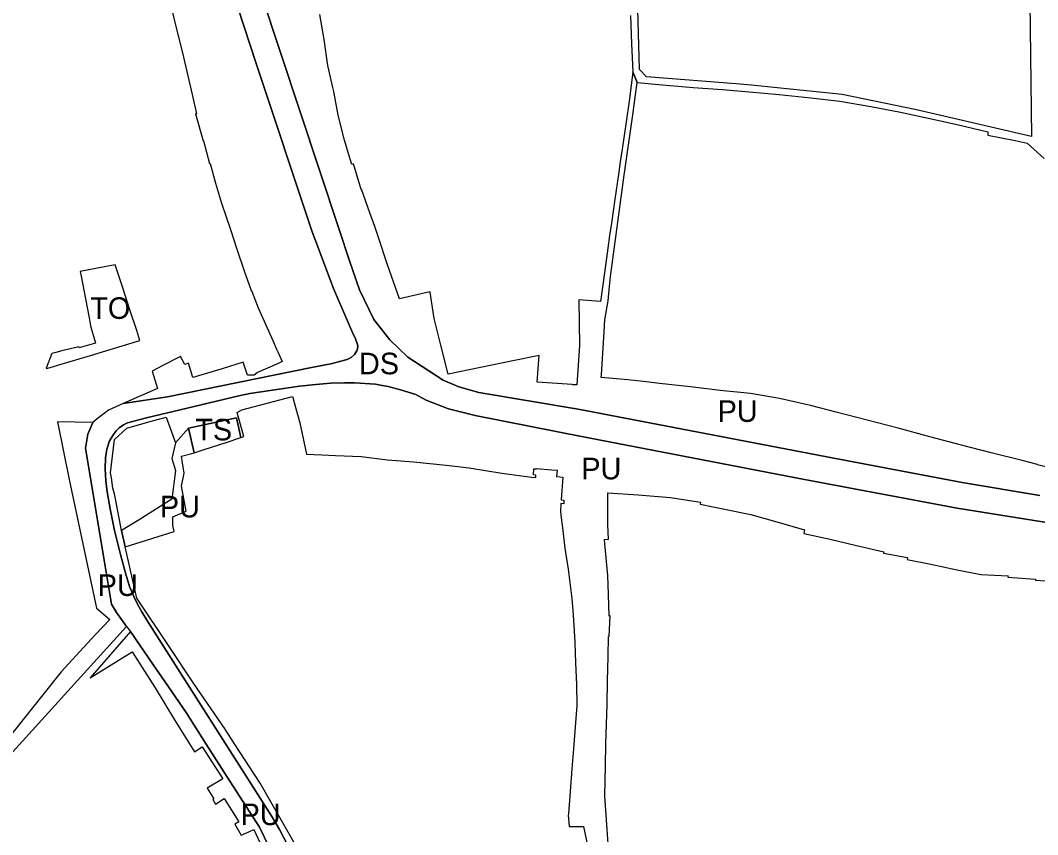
# Model space of a CAD drawing. Extents: x -521047 to -518054, y -1194945 to -1189555.
# Drawn here: x -520049.7 to -519578, y -1191998.4 to -1191620.9 of the extents above; entities that cross this region are included whole.
import ezdxf

# ---------------------------------------------------------------- set-up
doc = ezdxf.new("R2010")
doc.units = 0
for name, color, linetype in [('90320013', 7, 'Continuous'), ('90410013', 7, 'Continuous'), ('90430013', 7, 'Continuous'), ('90450013', 7, 'Continuous')]:
    doc.layers.add(name, color=color, linetype=linetype)

msp = doc.modelspace()

# ---------------------------------------------------------------- linework, layer by layer
at = {"layer": '90320013'}
for points in [[(-519951.7, -1191606.35), (-519940.4, -1191640.9), (-519914.37, -1191718.97), (-519913.17, -1191722.18), (-519904.59, -1191745.15), (-519904.11, -1191746.27), (-519899.31, -1191757.43), (-519895.67, -1191765.56), (-519894.32, -1191768.58), (-519893.35, -1191771.13), (-519893.23, -1191772.14), (-519893.35, -1191773.17), (-519893.72, -1191774.12), (-519894.86, -1191775.8), (-519896.34, -1191777.19), (-519898.15, -1191778.09), (-519905.8, -1191780.08), (-519914.66, -1191781.8), (-519932.25, -1191785.42), (-519981.45, -1191795.45), (-520002.03, -1191798.56), (-520008.78, -1191801.57), (-520014.11, -1191805.56), (-520016.05, -1191807.34), (-520018.47, -1191812.73), (-520019.56, -1191819.22), (-520007.5, -1191891.48), (-520005.16, -1191895.35), (-520000.5, -1191901.98), (-519998.7, -1191904.19), (-519987.91, -1191919.82), (-519982.66, -1191927.42), (-519972.8, -1191941.71), (-519963.53, -1191956.53), (-519954, -1191971.37), (-519938.91, -1191994.89), (-519934.5, -1192003.88)], [(-519577.08, -1191841.18), (-519613.12, -1191835.08), (-519672.49, -1191823.8), (-519791.06, -1191801.12), (-519837.21, -1191793.39), (-519846.4, -1191790.82), (-519853.69, -1191787.65), (-519869.99, -1191777.11), (-519878.44, -1191768.99), (-519885.81, -1191759.52), (-519892.42, -1191745.79), (-519897.31, -1191731.93), (-519901.82, -1191718.32), (-519929.33, -1191635.28), (-519937.84, -1191609.04)], [(-519925.88, -1192003.11), (-519929.61, -1191996.06), (-519933.13, -1191990.02), (-519990.79, -1191899.38), (-519993.42, -1191895.12), (-519995.33, -1191891.61), (-519997.06, -1191888.01), (-519999.05, -1191883.41), (-520000.86, -1191877.69), (-520003.3, -1191868.48), (-520006.03, -1191857.38), (-520008.1, -1191847.41), (-520009.43, -1191839.41), (-520010.05, -1191834.36), (-520010.35, -1191828.8), (-520010.25, -1191823.71), (-520009.68, -1191819.64), (-520008.43, -1191815.77), (-520006.6, -1191812.84), (-520005.35, -1191811.24), (-520003.94, -1191809.78), (-520001.94, -1191808.4), (-520000.09, -1191807.54), (-519991.21, -1191805.18), (-519972.41, -1191800.67), (-519948.39, -1191794.95), (-519943.26, -1191793.93), (-519920.23, -1191790.55), (-519912.66, -1191789.74), (-519905.97, -1191789.15), (-519899.49, -1191788.87), (-519894.81, -1191788.88), (-519885.06, -1191789.58), (-519881.98, -1191790.14), (-519879.25, -1191790.68), (-519873.45, -1191792.22), (-519866.29, -1191794.43), (-519861.49, -1191796.98), (-519851.18, -1191801.06), (-519838.85, -1191804.06), (-519800.55, -1191811.63), (-519797.43, -1191812.24), (-519781.44, -1191815.36), (-519686.16, -1191833.74), (-519615.32, -1191846.99), (-519568.13, -1191854.57)]]:
    msp.add_lwpolyline(points, dxfattribs=at)
at = {"layer": '90410013'}
msp.add_lwpolyline([(-519969.19, -1191821.4), (-519964.89, -1191820), (-519964.46, -1191819.86), (-519954.33, -1191816.57), (-519947.47, -1191814.34), (-519949.53, -1191805.16), (-519971.77, -1191809.96), (-519969.19, -1191821.4)], dxfattribs=at)
at = {"layer": '90430013'}
msp.add_lwpolyline([(-519994.31, -1191769.26), (-519995.78, -1191764.75), (-519998.92, -1191755.07), (-520002.37, -1191744.43), (-520005.69, -1191734.2), (-520010.73, -1191735.19), (-520021.93, -1191737.38), (-520021.53, -1191739.43), (-520018.69, -1191754.09), (-520017.89, -1191758.75), (-520017.24, -1191762.51), (-520014.83, -1191770.51), (-520022.41, -1191772.79), (-520022.59, -1191772.19), (-520028.49, -1191773.6), (-520029.39, -1191773.82), (-520033.33, -1191774.87), (-520035.11, -1191775.34), (-520037.79, -1191782.2), (-520037.58, -1191782.36), (-520034.75, -1191781.51), (-520031.92, -1191780.65), (-520017.18, -1191776.24), (-520002.44, -1191771.82), (-519994.31, -1191769.26)], dxfattribs=at)
at = {"layer": '90450013'}
for points in [[(-519583.09, -1191499.99), (-519580.83, -1191674.78), (-519586.89, -1191673.37), (-519634.15, -1191662.4), (-519668.73, -1191655.24), (-519698.78, -1191652.19), (-519710.66, -1191650.95), (-519716.05, -1191650.55), (-519759.34, -1191647.09), (-519762.65, -1191643.76), (-519765.6, -1191537.51)], [(-519979.91, -1191614.16), (-519977.29, -1191625.06), (-519974.61, -1191635.89), (-519972.14, -1191646.55), (-519970.12, -1191655.32), (-519968.1, -1191664.17), (-519968.45, -1191664.24), (-519965.03, -1191676.77), (-519964.74, -1191676.7), (-519962.09, -1191687.28), (-519961.74, -1191687.2), (-519959.25, -1191696.44), (-519956.45, -1191705.61), (-519952.36, -1191717.83), (-519949.34, -1191727.04), (-519945.95, -1191736.95), (-519942.66, -1191746.15), (-519942.51, -1191746.12), (-519939.38, -1191754.11), (-519932.66, -1191769.26), (-519930.88, -1191773.31), (-519930.29, -1191774.52), (-519928.26, -1191779.12), (-519930.56, -1191780.13), (-519939.82, -1191784.22), (-519939.96, -1191784.28), (-519941.27, -1191785.44), (-519944.46, -1191785.36), (-519946.34, -1191779.4), (-519956.07, -1191782.43), (-519969.69, -1191786.44), (-519971.72, -1191779.87), (-519973.38, -1191780.42), (-519975.46, -1191776.81), (-519983.97, -1191781.13), (-519988.61, -1191783.49), (-519986.18, -1191791.5), (-520002.03, -1191798.56), (-519981.45, -1191795.45), (-519932.25, -1191785.42), (-519914.66, -1191781.8), (-519905.8, -1191780.08), (-519898.15, -1191778.09), (-519896.34, -1191777.19), (-519894.86, -1191775.8), (-519893.72, -1191774.12), (-519893.35, -1191773.17), (-519893.23, -1191772.14), (-519893.35, -1191771.13), (-519894.32, -1191768.58), (-519895.67, -1191765.56), (-519899.31, -1191757.43), (-519904.11, -1191746.27), (-519904.59, -1191745.15), (-519913.17, -1191722.18), (-519914.37, -1191718.97), (-519940.4, -1191640.9), (-519951.7, -1191606.35)], [(-519937.84, -1191609.04), (-519929.33, -1191635.28), (-519901.82, -1191718.32), (-519897.31, -1191731.93), (-519892.42, -1191745.79), (-519885.81, -1191759.52), (-519878.44, -1191768.99), (-519869.99, -1191777.11), (-519853.69, -1191787.65), (-519846.4, -1191790.82), (-519837.21, -1191793.39), (-519791.06, -1191801.12), (-519672.49, -1191823.8), (-519613.12, -1191835.08), (-519577.08, -1191841.18)], [(-519857.83, -1191759.18), (-519859.76, -1191746.93), (-519859.79, -1191746.71), (-519873.86, -1191750.05), (-519879.44, -1191734.23), (-519883.67, -1191721.51), (-519885.35, -1191716.54), (-519887.63, -1191710.07), (-519891.52, -1191699.22), (-519891.75, -1191699.3), (-519895.27, -1191687.47), (-519896.1, -1191687.72), (-519897.78, -1191682.21), (-519899.39, -1191676.45), (-519902.39, -1191664.91), (-519904.44, -1191653.91), (-519904.97, -1191651.47), (-519905.14, -1191650.69), (-519907.1, -1191641.81), (-519908.85, -1191629.77), (-519910.89, -1191618.15)], [(-519766.89, -1191618.67), (-519766.35, -1191631.77), (-519765.78, -1191644.8), (-519763.68, -1191649.71), (-519752.06, -1191650.85), (-519744.88, -1191651.4), (-519737.81, -1191651.98), (-519724.23, -1191652.91), (-519711.85, -1191654), (-519697.86, -1191655.3), (-519683.18, -1191656.8), (-519669.7, -1191658.43), (-519655.45, -1191660.89), (-519641.67, -1191663.45), (-519628.05, -1191666.43), (-519614.74, -1191669.31), (-519601.15, -1191672.57), (-519601.22, -1191674.07)], [(-519570.61, -1191828.79), (-519578.11, -1191827), (-519578.06, -1191826.76), (-519585.29, -1191825.02), (-519599.53, -1191821.47), (-519613.42, -1191817.84), (-519627.98, -1191813.98), (-519642.75, -1191809.97), (-519657.16, -1191806.23), (-519671.44, -1191802.55), (-519683.4, -1191799.48), (-519697.75, -1191796.23), (-519711.2, -1191793.91), (-519725.26, -1191792.48), (-519738.98, -1191790.84), (-519753.35, -1191789.21), (-519760.76, -1191788.37), (-519768.03, -1191787.55), (-519780.42, -1191786.48), (-519780.33, -1191785.08), (-519779.24, -1191767.92), (-519778.72, -1191759.69), (-519777.16, -1191750.99), (-519776.57, -1191744.36), (-519776.12, -1191739.58), (-519769.69, -1191692.63), (-519765.97, -1191665.84), (-519763.68, -1191649.71), (-519765.78, -1191644.8), (-519767.31, -1191657.3), (-519769.05, -1191669.09), (-519770.71, -1191680.67), (-519771.54, -1191686.47), (-519772.38, -1191692.31), (-519774.06, -1191703.84), (-519775.69, -1191714.88), (-519776.58, -1191720.64), (-519777.34, -1191726.5), (-519778.77, -1191736.84), (-519780.68, -1191751.27), (-519790.84, -1191750.42), (-519790.49, -1191771.67), (-519791.66, -1191789.94), (-519793.49, -1191789.8), (-519793.87, -1191789.77), (-519810.07, -1191788.65), (-519809.2, -1191776.23), (-519821.34, -1191778.8), (-519851.31, -1191784.91), (-519854.69, -1191771.56), (-519857.83, -1191759.18)], [(-519601.22, -1191674.07), (-519588.45, -1191676.67), (-519582.88, -1191677.87), (-519574.98, -1191684.89)], [(-519568.13, -1191854.57), (-519615.32, -1191846.99), (-519686.16, -1191833.74), (-519781.44, -1191815.36), (-519797.43, -1191812.24), (-519800.55, -1191811.63), (-519838.85, -1191804.06), (-519851.18, -1191801.06), (-519861.49, -1191796.98), (-519866.29, -1191794.43), (-519873.45, -1191792.22), (-519879.25, -1191790.68), (-519881.98, -1191790.14), (-519885.06, -1191789.58), (-519894.81, -1191788.88), (-519899.49, -1191788.87), (-519905.97, -1191789.15), (-519912.66, -1191789.74), (-519920.23, -1191790.55), (-519943.26, -1191793.93), (-519948.39, -1191794.95), (-519972.41, -1191800.67), (-519991.21, -1191805.18), (-520000.09, -1191807.54), (-520001.94, -1191808.4), (-520003.94, -1191809.78), (-520005.35, -1191811.24), (-520006.6, -1191812.84), (-520008.43, -1191815.77), (-520009.68, -1191819.64), (-520010.25, -1191823.71), (-520010.35, -1191828.8), (-520010.05, -1191834.36), (-520009.43, -1191839.41), (-520008.1, -1191847.41), (-520006.03, -1191857.38), (-520003.3, -1191868.48), (-520000.86, -1191877.69), (-519999.05, -1191883.41), (-519997.06, -1191888.01), (-519995.33, -1191891.61), (-519993.42, -1191895.12), (-519990.79, -1191899.38), (-519933.13, -1191990.02), (-519929.61, -1191996.06), (-519925.88, -1192003.11)], [(-519922.3, -1192002.97), (-519926.15, -1191996.16), (-519929.81, -1191989.73), (-519938.46, -1191974.54), (-519950.46, -1191956.33), (-519954.62, -1191949.85), (-519954.81, -1191949.55), (-519969.38, -1191928.14), (-519980.73, -1191911.17), (-519995.77, -1191888.7), (-520001.16, -1191864.95), (-520002.87, -1191857.4), (-520004.91, -1191846.02), (-520006.13, -1191840.44), (-520006.77, -1191837.77), (-520007.53, -1191832.99), (-520007.87, -1191830.72), (-520006.13, -1191815.28), (-520000.29, -1191809.99), (-519990.1, -1191807.06), (-519982.11, -1191804.83), (-519977.82, -1191816.74), (-519971.77, -1191809.96), (-519949.53, -1191805.16), (-519947.47, -1191814.34), (-519946.08, -1191813.89), (-519949.17, -1191802.72), (-519947.02, -1191801.53), (-519923.55, -1191795.32), (-519920.18, -1191807.45), (-519916.99, -1191822.06), (-519910, -1191822.35), (-519903.53, -1191822.7), (-519891.77, -1191823.12), (-519879.47, -1191824.6), (-519867.4, -1191825.52), (-519859.82, -1191826.39), (-519852.26, -1191827.17), (-519841.63, -1191828.37), (-519826.51, -1191830.83), (-519812.65, -1191832.65), (-519810.72, -1191832.9), (-519810.64, -1191831.71), (-519811.81, -1191831.63), (-519811.64, -1191828.75), (-519810.47, -1191828.81), (-519810.4, -1191828.64), (-519803.44, -1191829.29), (-519800.86, -1191829.48), (-519801.12, -1191832.4), (-519798.26, -1191832.6), (-519799.02, -1191843.18), (-519797.75, -1191843.28), (-519797.78, -1191845.05), (-519799.16, -1191844.95), (-519799.31, -1191848.53), (-519799.09, -1191850.3), (-519798.21, -1191857.36), (-519797.26, -1191865.55), (-519795.65, -1191875.39), (-519794.06, -1191888.87), (-519793.57, -1191894.67), (-519793.21, -1191898.99), (-519792.58, -1191909.1), (-519792.46, -1191914.09), (-519792.35, -1191918.76), (-519791.81, -1191928.79), (-519791.7, -1191938.6), (-519792.42, -1191948.53), (-519793.24, -1191958.55), (-519793.98, -1191967.86), (-519794.81, -1191978.45), (-519795.61, -1191988.68), (-519795.66, -1191989.32), (-519795.2, -1191994.6), (-519788.63, -1191994.63), (-519786.7, -1192003.43)], [(-520055.94, -1191954.58), (-520056.08, -1191954.75), (-520059.24, -1191958.73), (-520064.17, -1191960.26), (-520060.15, -1191966.67), (-520056.79, -1191961.78), (-520054.76, -1191961.68), (-520027.63, -1191931.83), (-520000.5, -1191901.98), (-520005.16, -1191895.35), (-520007.5, -1191891.48), (-520019.56, -1191819.22), (-520018.47, -1191812.73), (-520016.05, -1191807.34), (-520032.53, -1191806.97), (-520029.72, -1191820.71), (-520027.04, -1191833.79), (-520014.4, -1191893.4), (-520008.2, -1191898.59), (-520015.01, -1191905.83), (-520030.81, -1191922.99), (-520052.53, -1191950.29), (-520055.94, -1191954.58)], [(-519969.19, -1191821.4), (-519971.77, -1191809.96), (-519977.82, -1191816.74), (-519979.51, -1191824.01), (-519977.77, -1191829.65), (-519979.5, -1191842.89), (-519984.85, -1191846.32), (-519994.64, -1191852.42), (-520002.87, -1191857.4), (-520001.16, -1191864.95), (-519978.42, -1191857.87), (-519979.08, -1191855.05), (-519979.08, -1191851.13), (-519972.88, -1191848.39), (-519974.94, -1191836.82), (-519973.76, -1191830.79), (-519974.61, -1191826.1), (-519975, -1191822.92), (-519970.16, -1191821.74), (-519969.19, -1191821.4)], [(-519777.19, -1192002.68), (-519778.7, -1191980.47), (-519778.43, -1191966.53), (-519778.22, -1191956.26), (-519777.71, -1191938.09), (-519777.42, -1191927.06), (-519777.14, -1191915.84), (-519777, -1191906.55), (-519776.67, -1191906.56), (-519776.29, -1191897.03), (-519776.74, -1191897.06), (-519777.02, -1191887.04), (-519777.4, -1191878.33), (-519778.7, -1191863.57), (-519778.81, -1191861.51), (-519777.05, -1191861.35), (-519777.39, -1191854.74), (-519777.26, -1191839.95), (-519763.31, -1191840.91), (-519748.24, -1191842.1), (-519734.35, -1191844.34), (-519734.51, -1191845.18), (-519722.48, -1191847.67), (-519710.96, -1191849.95), (-519698.96, -1191853.36), (-519686.19, -1191857.13), (-519686.46, -1191858.75), (-519674.32, -1191861.45), (-519662.1, -1191864.32), (-519649.44, -1191867.3), (-519649.57, -1191867.84), (-519638.43, -1191869.9), (-519638.61, -1191870.85), (-519627.5, -1191873.03), (-519616.1, -1191875.45), (-519604.45, -1191877.74), (-519591.76, -1191878.43), (-519591.8, -1191878.98), (-519578.97, -1191879.98), (-519579, -1191880.45), (-519565.6, -1191881.32)], [(-519934.5, -1192003.88), (-519938.91, -1191994.89), (-519954, -1191971.37), (-519963.53, -1191956.53), (-519972.8, -1191941.71), (-519982.66, -1191927.42), (-519987.91, -1191919.82), (-519998.7, -1191904.19), (-520017.32, -1191925.76), (-519997.93, -1191913.6), (-519992.15, -1191922.67), (-519987.2, -1191930.37), (-519978.25, -1191945.23), (-519968.94, -1191959.95), (-519965.42, -1191957.72), (-519960.63, -1191965.1), (-519955.84, -1191972.48), (-519963.05, -1191976.83), (-519959.95, -1191981.75), (-519960.54, -1191982.17), (-519959.29, -1191984.22), (-519955.18, -1191981.65), (-519948.46, -1191992.45), (-519950.32, -1191993.61), (-519947.28, -1191998.71), (-519945.87, -1191998.03), (-519945.47, -1191997.84), (-519941.43, -1191996.02), (-519937.63, -1192004.36)]]:
    msp.add_lwpolyline(points, dxfattribs=at)

# ---------------------------------------------------------------- texts
at = {"layer": '90320013'}
msp.add_text('DS', height=10, rotation=0, dxfattribs=at).set_placement((-519892.72, -1191784.98))
at = {"layer": '90410013'}
msp.add_text('TS', height=10, rotation=0, dxfattribs=at).set_placement((-519968.61, -1191815.63))
at = {"layer": '90430013'}
msp.add_text('TO', height=10, rotation=0, dxfattribs=at).set_placement((-520017.3, -1191759.3))
at = {"layer": '90450013'}
for rotation, p in [(360, (-519726.43, -1191807.05)), (0, (-519789.62, -1191833.68)), (360, (-519985.04, -1191851.33)), (0, (-520013.84, -1191887.75)), (0, (-519947.61, -1191993.98))]:
    msp.add_text('PU', height=10, rotation=rotation, dxfattribs=at).set_placement(p)

doc.saveas('drawing.dxf')
